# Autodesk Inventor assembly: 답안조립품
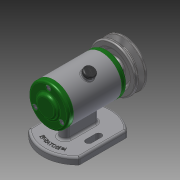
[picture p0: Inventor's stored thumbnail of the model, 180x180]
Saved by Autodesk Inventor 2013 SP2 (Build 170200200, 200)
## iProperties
Created: 2022-02
Part Number: 답안조립품
Document SubType Name: Assembly
Designer: a
Author: a
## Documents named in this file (14)
- C:\Users\a\Desktop\720206V1017\답안조립품.iam
- C:\Users\a\Desktop\720206V1017\본체.ipt
- C:\Users\a\Desktop\720206V1017\V벨트풀리.ipt
- C:\Users\a\Desktop\720206V1017\고무 캡.ipt
- C:\Users\a\Desktop\720206V1017\너트 M8.ipt
- C:\Users\a\Desktop\720206V1017\뒤커버.ipt
- C:\Users\a\Desktop\720206V1017\베어링 6002.ipt
- C:\Users\a\Desktop\720206V1017\볼트 M4 x 10.ipt
- C:\Users\a\Desktop\720206V1017\스프링와셔 8.ipt
- C:\Users\a\Desktop\720206V1017\앞커버.ipt
- C:\Users\a\Desktop\720206V1017\오일 실 15 x 25 x 7.ipt
- C:\Users\a\Desktop\720206V1017\축.ipt
- C:\Users\a\Desktop\720206V1017\키 3 x 3 x 12.ipt
- C:\Users\a\Desktop\720206V1017\평와셔 8 x 17.ipt
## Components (2 placed, 2 different names)
1. V벨트풀리:1
2. 고무 캡:1
